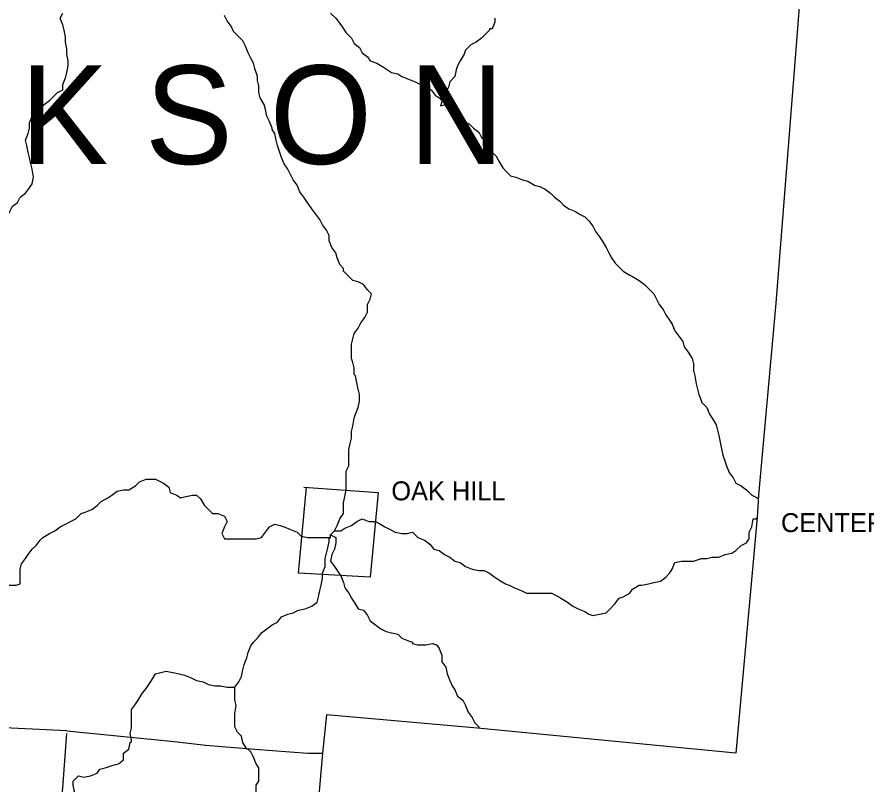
# Model space of a CAD drawing. Extents: x 0 to 34, y 0 to 22.
# Drawn here: x 7.227 to 8.101, y 16.826 to 17.615 of the extents above; entities that cross this region are included whole.
import ezdxf

# ---------------------------------------------------------------- set-up
doc = ezdxf.new("R2010")
doc.units = 0
doc.layers.add('Default', color=7, linetype='Continuous')
doc.layers.add('TR_Turning_Path1', color=7, linetype='Continuous')

msp = doc.modelspace()

# ---------------------------------------------------------------- linework, layer by layer
at = {"layer": 'Default'}
for points in [[(8.07464, 18.18519), (8.07192, 18.14702), (8.05964, 17.9875), (8.02965, 17.59483), (8.00783, 17.32079), (7.99011, 17.12309), (7.98875, 17.09991), (7.96693, 16.85722), (7.70107, 16.88313), (7.54564, 16.89676)], [(7.24296, 17.45849), (7.24159, 17.46394), (7.24023, 17.47076), (7.23887, 17.47622), (7.2375, 17.48303), (7.23614, 17.48849), (7.23887, 17.4953), (7.24023, 17.50076), (7.24023, 17.50621), (7.24296, 17.51303), (7.24705, 17.51575), (7.25114, 17.51985), (7.25523, 17.5253), (7.26068, 17.52939), (7.26477, 17.53348), (7.26886, 17.53757), (7.27431, 17.5403), (7.27431, 17.54575), (7.27704, 17.55257), (7.2784, 17.55802), (7.27977, 17.56484), (7.27977, 17.57029), (7.2784, 17.57711), (7.2784, 17.58256), (7.27704, 17.58938), (7.27704, 17.59483), (7.27568, 17.60165), (7.27431, 17.6071), (7.27159, 17.61392), (7.27431, 17.61937)], [(7.54973, 17.61937), (7.55518, 17.61392), (7.55927, 17.60847), (7.56336, 17.60301), (7.56609, 17.59892), (7.57154, 17.59347), (7.57427, 17.58802), (7.57972, 17.58393), (7.58245, 17.57847), (7.5879, 17.57438), (7.59063, 17.57029), (7.59745, 17.56756), (7.60426, 17.56347), (7.60835, 17.56075), (7.61244, 17.55802), (7.61926, 17.55666), (7.62335, 17.55393), (7.63017, 17.5512), (7.63698, 17.54848), (7.64244, 17.54575), (7.64789, 17.54302), (7.65335, 17.5403), (7.65744, 17.53484), (7.66153, 17.53212), (7.66698, 17.52666), (7.66698, 17.52666), (7.66834, 17.5253)], [(7.48973, 17.50076), (7.48701, 17.50757), (7.48428, 17.51303), (7.48292, 17.51985), (7.48155, 17.5253), (7.47746, 17.53212), (7.4761, 17.53757), (7.4761, 17.54439), (7.47474, 17.54984), (7.47474, 17.55393), (7.47201, 17.56211), (7.47065, 17.56756), (7.46792, 17.57302), (7.46519, 17.57847), (7.46247, 17.58529), (7.45974, 17.59074), (7.45565, 17.59483), (7.4502, 17.60029), (7.44747, 17.60574), (7.44338, 17.61119), (7.44065, 17.61665)], [(7.71879, 17.61392), (7.71879, 17.60983), (7.71606, 17.60301)], [(7.71606, 17.60301), (7.71334, 17.60301), (7.71334, 17.60165), (7.70925, 17.59756), (7.70516, 17.59347), (7.6997, 17.58938), (7.69425, 17.58665), (7.68879, 17.5812), (7.68743, 17.57711), (7.68334, 17.57029), (7.68061, 17.56484), (7.67925, 17.56075), (7.67789, 17.55393), (7.67243, 17.54848), (7.67107, 17.54302), (7.66834, 17.53757)], [(7.66834, 17.53757), (7.66698, 17.53348), (7.66425, 17.52803), (7.66289, 17.52394), (7.66834, 17.5253)], [(7.66834, 17.5253), (7.67243, 17.52121), (7.67789, 17.51712), (7.68334, 17.51303), (7.68743, 17.50757), (7.69288, 17.50485), (7.69697, 17.50076), (7.70243, 17.49667), (7.70516, 17.49121), (7.70925, 17.48712), (7.71197, 17.48031), (7.71606, 17.47622), (7.72015, 17.47213), (7.72288, 17.46667), (7.72697, 17.45985), (7.73106, 17.45576), (7.73515, 17.45167), (7.7406, 17.45031), (7.74742, 17.44758), (7.75288, 17.44622), (7.75969, 17.44213), (7.76515, 17.44077), (7.76515, 17.44077)], [(7.52518, 17.42577), (7.52246, 17.42986), (7.51837, 17.43531), (7.51564, 17.44213), (7.51155, 17.44758), (7.50882, 17.45304), (7.5061, 17.45849), (7.50201, 17.46394), (7.49928, 17.47076), (7.49792, 17.47485), (7.49519, 17.48303), (7.49383, 17.48849), (7.49246, 17.4953), (7.48973, 17.49939), (7.48973, 17.50076)], [(7.19933, 17.33715), (7.20069, 17.34396), (7.19933, 17.35078), (7.19796, 17.3576), (7.19796, 17.36442), (7.19796, 17.36987), (7.19933, 17.37669), (7.20205, 17.38214), (7.20478, 17.38896), (7.20614, 17.39441), (7.21023, 17.3985), (7.21296, 17.40395), (7.21705, 17.40941), (7.21978, 17.41486), (7.2225, 17.42032), (7.22796, 17.42441), (7.23069, 17.42986), (7.23614, 17.43395), (7.24023, 17.4394), (7.24296, 17.44349), (7.24432, 17.45031), (7.24296, 17.45849), (7.24296, 17.45849)], [(7.76515, 17.44077), (7.7706, 17.43804), (7.77605, 17.43395), (7.78014, 17.42986), (7.7856, 17.42577), (7.78969, 17.42168), (7.79514, 17.41759), (7.80196, 17.41486), (7.80605, 17.41214), (7.8115, 17.40941), (7.81559, 17.40532), (7.81968, 17.39986), (7.82241, 17.39441), (7.8265, 17.38896), (7.82923, 17.38487), (7.83332, 17.37805), (7.83604, 17.3726), (7.83877, 17.36714), (7.84286, 17.36169), (7.84695, 17.3576), (7.85104, 17.35351), (7.85786, 17.34942), (7.86059, 17.34805), (7.86059, 17.34805)], [(7.56336, 17.35623), (7.55927, 17.36033), (7.55654, 17.36714), (7.55518, 17.3726), (7.55109, 17.37805), (7.54836, 17.38487), (7.54836, 17.39032), (7.54564, 17.39577), (7.54154, 17.40123), (7.53882, 17.40668), (7.53473, 17.41214), (7.53064, 17.41759), (7.52518, 17.42577), (7.52518, 17.42577)], [(7.57427, 17.24716), (7.57427, 17.25398), (7.5729, 17.25943), (7.57154, 17.26352), (7.57154, 17.27034), (7.57154, 17.27852), (7.5729, 17.28397), (7.57427, 17.28943), (7.57836, 17.29488), (7.58108, 17.30033), (7.58517, 17.30579), (7.5879, 17.31124), (7.5879, 17.31942), (7.59063, 17.32488), (7.59199, 17.33033), (7.5879, 17.33442), (7.58381, 17.33987), (7.57836, 17.3426), (7.5729, 17.34396), (7.56745, 17.34942), (7.56336, 17.35351), (7.56336, 17.35351), (7.56336, 17.35623)], [(7.57427, 17.24716), (7.57427, 17.25398), (7.5729, 17.25943), (7.57154, 17.26352), (7.57154, 17.27034), (7.57154, 17.27852), (7.5729, 17.28397), (7.57427, 17.28943), (7.57836, 17.29488), (7.58108, 17.30033), (7.58517, 17.30579), (7.5879, 17.31124), (7.5879, 17.31942), (7.59063, 17.32488), (7.59199, 17.33033), (7.5879, 17.33442), (7.58381, 17.33987), (7.57836, 17.3426), (7.5729, 17.34396), (7.56745, 17.34942), (7.56336, 17.35351), (7.56336, 17.35351), (7.56336, 17.35623)], [(7.86059, 17.34805), (7.8674, 17.34396), (7.87286, 17.33987), (7.87695, 17.33578), (7.8824, 17.33033), (7.88513, 17.32488), (7.88785, 17.31942), (7.89194, 17.31397), (7.89467, 17.30852), (7.89876, 17.30306), (7.90149, 17.29897), (7.90421, 17.29215), (7.90831, 17.2867), (7.9124, 17.28125), (7.91376, 17.27579), (7.91785, 17.27034), (7.92194, 17.26352), (7.9233, 17.25807), (7.9233, 17.25125), (7.92467, 17.2458), (7.92603, 17.23762), (7.92739, 17.23216), (7.92876, 17.22671), (7.93148, 17.21989), (7.93148, 17.21853), (7.93148, 17.21853)], [(7.2784, 16.8804), (7.16388, 16.88585), (7.05753, 16.89404), (7.00436, 16.89676), (6.96073, 16.89949), (6.92528, 16.90222), (6.9021, 16.90494), (6.8871, 16.90767), (6.88574, 16.9363), (6.88301, 16.97448), (6.88574, 16.98811), (6.8871, 16.99493), (6.89392, 17.04265), (6.89801, 17.10537), (6.90074, 17.1599), (6.90619, 17.22671), (6.91301, 17.31261), (6.80802, 17.32079), (6.72349, 17.32624)], [(7.56881, 17.16945), (7.57018, 17.17626), (7.57154, 17.18172), (7.57154, 17.18853), (7.5729, 17.19399), (7.57427, 17.20217), (7.57563, 17.20626), (7.57836, 17.21308), (7.57972, 17.21989), (7.57972, 17.22671), (7.57836, 17.23216), (7.57699, 17.23898), (7.57563, 17.2458), (7.57427, 17.24716)], [(7.93148, 17.21853), (7.93694, 17.21308), (7.93966, 17.20626), (7.94239, 17.20217), (7.94648, 17.19535), (7.94784, 17.1899), (7.94921, 17.18444), (7.95057, 17.17763), (7.95193, 17.17081), (7.9533, 17.16399), (7.95602, 17.15718), (7.95739, 17.15309), (7.96012, 17.14627), (7.96421, 17.14081), (7.96693, 17.13536), (7.97239, 17.13263), (7.97784, 17.12854), (7.98329, 17.12309), (7.98875, 17.12036), (7.99011, 17.119)], [(7.55382, 17.08628), (7.55654, 17.09173), (7.55927, 17.09855), (7.56336, 17.104), (7.56336, 17.10809), (7.56336, 17.11491), (7.56472, 17.12173), (7.56609, 17.12854), (7.56609, 17.13536), (7.56609, 17.14081), (7.56609, 17.14763), (7.56881, 17.15309), (7.56881, 17.16127), (7.56881, 17.16808), (7.56881, 17.16945)], [(7.23887, 17.06174), (7.24296, 17.06719), (7.24705, 17.07128), (7.25114, 17.07673), (7.25386, 17.07946), (7.26068, 17.08355), (7.26613, 17.08628), (7.27159, 17.09037), (7.27704, 17.09309), (7.2825, 17.09582), (7.28795, 17.09855), (7.2934, 17.104), (7.29749, 17.10537), (7.30431, 17.10809), (7.30976, 17.11218), (7.31385, 17.11627), (7.32067, 17.12036), (7.32476, 17.12309), (7.33021, 17.12718), (7.33703, 17.12854), (7.34249, 17.12854), (7.3493, 17.13263), (7.35339, 17.13672), (7.36021, 17.13945), (7.36703, 17.13945), (7.36975, 17.13945), (7.37248, 17.13809)], [(7.37248, 17.13809), (7.37793, 17.13536), (7.38339, 17.13127), (7.38475, 17.12582), (7.39157, 17.12309), (7.39566, 17.12036), (7.40111, 17.12173), (7.40793, 17.12309), (7.41202, 17.12309), (7.41611, 17.119), (7.4202, 17.11218), (7.42429, 17.10809), (7.42838, 17.104), (7.43383, 17.104), (7.44065, 17.10128), (7.44338, 17.09582), (7.44065, 17.09037), (7.43793, 17.08355), (7.44065, 17.0781), (7.44065, 17.0781), (7.44065, 17.0781)], [(7.52246, 17.13127), (7.59881, 17.12582), (7.59063, 17.03856), (7.517, 17.04265), (7.52518, 17.13127)], [(7.55382, 17.08628), (7.56063, 17.08628), (7.56472, 17.089), (7.57154, 17.09173), (7.57699, 17.09582), (7.58245, 17.09855), (7.58926, 17.09582), (7.59608, 17.09582), (7.59881, 17.09446), (7.60563, 17.09037), (7.61108, 17.08764), (7.61653, 17.08491), (7.62335, 17.08355), (7.6288, 17.08355), (7.63426, 17.08491), (7.63971, 17.07946), (7.64653, 17.07673), (7.65198, 17.07264), (7.65607, 17.06719), (7.66153, 17.06583), (7.66698, 17.06174), (7.67243, 17.05901), (7.67789, 17.05492), (7.68334, 17.05356), (7.68879, 17.04947), (7.69561, 17.04674), (7.70243, 17.04537), (7.70788, 17.04537), (7.71334, 17.04265), (7.71879, 17.03856), (7.72288, 17.03583), (7.7297, 17.03174), (7.73379, 17.03038)], [(7.87013, 17.03038), (7.87695, 17.03174), (7.8824, 17.0331), (7.88922, 17.03447), (7.89467, 17.03856), (7.89876, 17.04265), (7.90149, 17.04674), (7.90421, 17.05356), (7.91103, 17.05492), (7.91785, 17.05492), (7.9233, 17.05492), (7.93148, 17.05765), (7.93694, 17.05765), (7.94239, 17.05901), (7.94921, 17.05901), (7.95602, 17.06174), (7.96284, 17.0631), (7.96693, 17.06583), (7.97239, 17.07128), (7.97784, 17.07401), (7.98057, 17.0781), (7.98057, 17.08491), (7.98329, 17.09037), (7.98466, 17.09855), (7.98875, 17.09855), (7.98875, 17.09991)], [(7.44065, 17.0781), (7.44747, 17.0781), (7.45292, 17.0781), (7.45974, 17.0781), (7.46792, 17.0781), (7.47337, 17.0781), (7.47883, 17.07946), (7.48292, 17.08491), (7.48701, 17.09037), (7.49246, 17.09309), (7.49792, 17.09173), (7.50201, 17.09037), (7.50882, 17.08764), (7.51564, 17.08491), (7.51973, 17.08082), (7.52655, 17.07946), (7.53336, 17.07946), (7.54018, 17.07946), (7.547, 17.07946), (7.54973, 17.07946)], [(7.54973, 17.08219), (7.55382, 17.08628)], [(7.45156, 16.92539), (7.45565, 16.93085), (7.45838, 16.9363), (7.45974, 16.94312), (7.4611, 16.94857), (7.46383, 16.95539), (7.46519, 16.96084), (7.46792, 16.96766), (7.47065, 16.97175), (7.47474, 16.97584), (7.47883, 16.98129), (7.48428, 16.98538), (7.48973, 16.98947), (7.49519, 16.9922), (7.49928, 16.99766), (7.5061, 17.00038), (7.51155, 17.00175), (7.517, 17.00447), (7.52382, 17.00584), (7.53064, 17.00856), (7.53609, 17.01265), (7.53745, 17.01811), (7.53882, 17.02492), (7.54018, 17.03038), (7.54154, 17.03719), (7.54154, 17.04265), (7.54427, 17.04947), (7.54427, 17.05765), (7.54564, 17.0631), (7.547, 17.06855), (7.54836, 17.07537), (7.54836, 17.0781), (7.54973, 17.07946)], [(7.54973, 17.07946), (7.54973, 17.08082), (7.54973, 17.08219)], [(7.54973, 17.07946), (7.54973, 17.08082), (7.54973, 17.08219)], [(7.54973, 17.08219), (7.55518, 17.07946), (7.55518, 17.07401), (7.55382, 17.06719), (7.55109, 17.06174), (7.54973, 17.05492), (7.55382, 17.04947), (7.55654, 17.04537), (7.56063, 17.03992), (7.56336, 17.0331), (7.56472, 17.02765), (7.56881, 17.0222), (7.57154, 17.01674), (7.57427, 17.01265), (7.57836, 17.00584), (7.58381, 17.00447), (7.5879, 16.99902), (7.59063, 16.99356), (7.59608, 16.98947), (7.60154, 16.98538), (7.60699, 16.98266), (7.61244, 16.98129), (7.61926, 16.97993), (7.62335, 16.97584), (7.63017, 16.97311), (7.63426, 16.97175), (7.63426, 16.97175), (7.63426, 16.97039)], [(7.20205, 17.0331), (7.20751, 17.03038), (7.21432, 17.03038), (7.21978, 17.03038), (7.22659, 17.03038), (7.23069, 17.03174), (7.23069, 17.03856), (7.23069, 17.04674), (7.23205, 17.05219), (7.23614, 17.05765), (7.23887, 17.06174), (7.23887, 17.06174)], [(7.73379, 17.03038), (7.73924, 17.02765), (7.74606, 17.02492), (7.75151, 17.0222), (7.75833, 17.0222), (7.76515, 17.0222), (7.7706, 17.0222), (7.77742, 17.0222), (7.78423, 17.01811), (7.78696, 17.01674), (7.79378, 17.01265), (7.79923, 17.00856), (7.80469, 17.00584), (7.8115, 17.00311), (7.81559, 17.00038), (7.81968, 16.99902), (7.8265, 17.00038), (7.83332, 17.00175), (7.83741, 17.00584), (7.84286, 17.01129), (7.84695, 17.01674), (7.85104, 17.01811), (7.85786, 17.0222), (7.86059, 17.02629), (7.8674, 17.03038), (7.86877, 17.03038), (7.87013, 17.03038)], [(7.63426, 16.97039), (7.63971, 16.96902), (7.64789, 16.96902), (7.65471, 16.97039), (7.6588, 16.96902), (7.66153, 16.96493), (7.66425, 16.95812), (7.66425, 16.9513), (7.66834, 16.94585), (7.66971, 16.93903), (7.67243, 16.93221), (7.67516, 16.92676), (7.67789, 16.92267), (7.68061, 16.91585), (7.68607, 16.91176), (7.68879, 16.90631), (7.69152, 16.89949), (7.69561, 16.89404), (7.69834, 16.88858), (7.70243, 16.88449), (7.70243, 16.88313)], [(7.34521, 16.87086), (7.34385, 16.87767), (7.34521, 16.88313), (7.34521, 16.88858), (7.34521, 16.89404), (7.34521, 16.90222), (7.3493, 16.90767), (7.35203, 16.91176), (7.35612, 16.91858), (7.36021, 16.92403), (7.36294, 16.92812), (7.36566, 16.93221), (7.36975, 16.93903), (7.37521, 16.94039), (7.38066, 16.94175), (7.38748, 16.94039), (7.3943, 16.93903), (7.39975, 16.93766), (7.40657, 16.93494), (7.41202, 16.93221), (7.41884, 16.93085), (7.42429, 16.92812), (7.43111, 16.92676), (7.43656, 16.92676), (7.44338, 16.92539), (7.44883, 16.92539), (7.4502, 16.92539), (7.45156, 16.92539)], [(7.46383, 16.86131), (7.45974, 16.86813), (7.45838, 16.87495), (7.45429, 16.87904), (7.45156, 16.88449), (7.45156, 16.89131), (7.45156, 16.89813), (7.45292, 16.90631), (7.45156, 16.91176), (7.45156, 16.91858), (7.45156, 16.92403), (7.45156, 16.92539)], [(7.54564, 16.89676), (7.54154, 16.85722)], [(7.23205, 16.42775), (7.2375, 16.48501), (7.24432, 16.48501), (7.25386, 16.58318), (7.25932, 16.64044), (7.26068, 16.66634), (7.26204, 16.67861), (7.2675, 16.75769), (7.27431, 16.82177), (7.2784, 16.87767), (7.2784, 16.87767), (7.2784, 16.87767)], [(7.2784, 16.8804), (7.38884, 16.86949), (7.42156, 16.8654), (7.47201, 16.86131), (7.52655, 16.85722), (7.54154, 16.85722), (7.54154, 16.85722)], [(7.27159, 16.80678), (7.27704, 16.8095), (7.2825, 16.81223), (7.28659, 16.81768), (7.28522, 16.8245), (7.28522, 16.82859), (7.29068, 16.83404), (7.29613, 16.83268), (7.30295, 16.83404), (7.30976, 16.83677), (7.31249, 16.84086), (7.31794, 16.84223), (7.32612, 16.84495), (7.33158, 16.84632), (7.33703, 16.85041), (7.33703, 16.85722), (7.34249, 16.86131), (7.34385, 16.86813), (7.34521, 16.86949), (7.34521, 16.87086)], [(7.47337, 16.74815), (7.4761, 16.7536), (7.4761, 16.76042), (7.4761, 16.76724), (7.4761, 16.77269), (7.4761, 16.77951), (7.4761, 16.78496), (7.4761, 16.79178), (7.4761, 16.7986), (7.47474, 16.80405), (7.47474, 16.81087), (7.47337, 16.81768), (7.47337, 16.8245), (7.4761, 16.82859), (7.4761, 16.83677), (7.4761, 16.84223), (7.47337, 16.84632), (7.47065, 16.85313), (7.46792, 16.85859), (7.46519, 16.86131), (7.46383, 16.86131)], [(7.54154, 16.85722), (7.51564, 16.55863), (7.8674, 16.53), (7.85786, 16.39639), (7.92603, 16.39093), (7.9124, 16.21778), (7.90558, 16.12234), (8.23689, 16.10189), (8.27507, 16.0978), (8.32415, 16.09507)]]:
    msp.add_lwpolyline(points, dxfattribs=at)

# ---------------------------------------------------------------- texts
for s, height, p in [('OAK HILL', 0.019502, (7.61244, 17.11764)), ('CENTERVILLE', 0.0195024, (8.01329, 17.08491))]:
    msp.add_text(s, height=height, dxfattribs=at).set_placement(p)
at = {"layer": 'TR_Turning_Path1'}
msp.add_text('J A C K S O N', height=0.1014887, dxfattribs=at).set_placement((6.8612, 17.46394))

doc.saveas('drawing.dxf')
